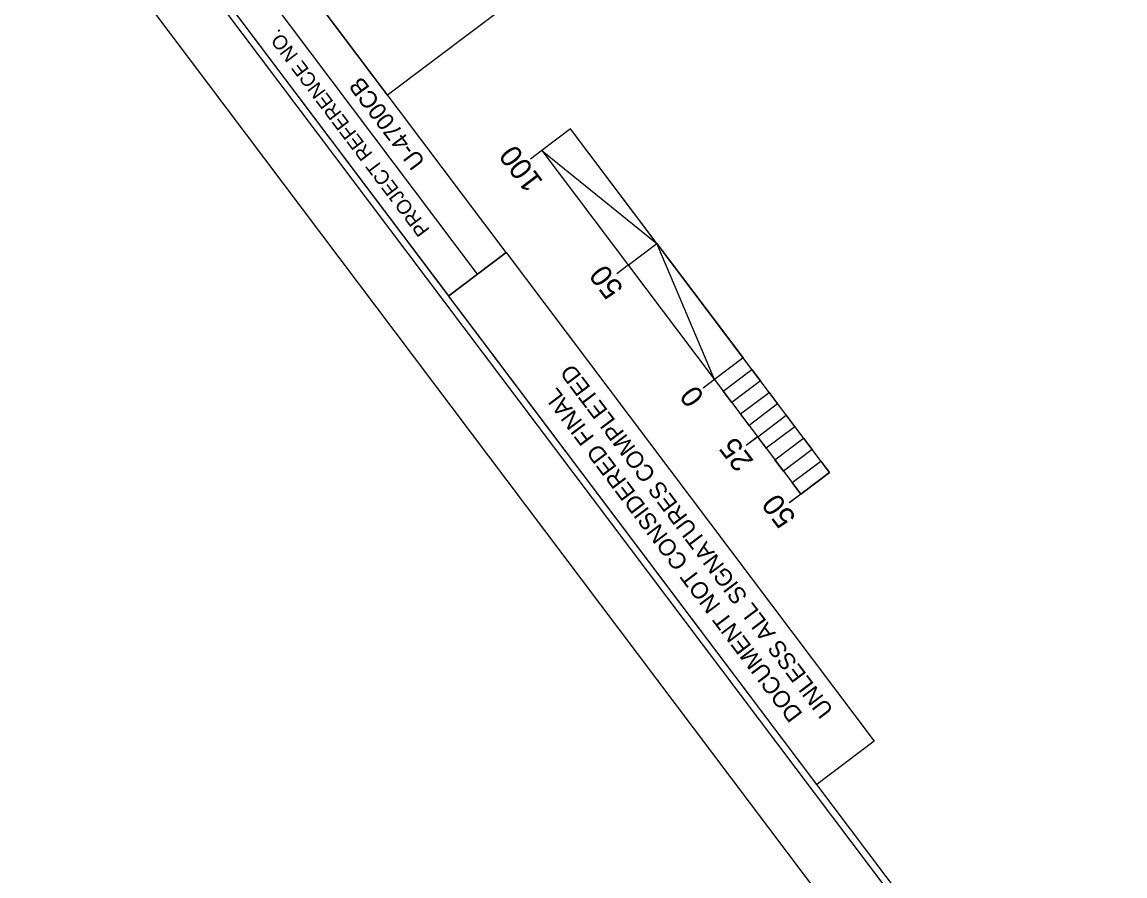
# Model space of a CAD drawing. Extents: x 1262917 to 1264804, y 775326 to 777329.
# Drawn here: x 1262916.5 to 1263300.5, y 776308.6 to 776605.9 of the extents above; entities that cross this region are included whole.
import ezdxf

# ---------------------------------------------------------------- set-up
doc = ezdxf.new("R2010")
doc.units = 0
for name, color, linetype in [('Sheet Data Field CELL', 7, 'Continuous'), ('Sheet Plan CELL', 7, 'Continuous'), ('Sheet Plot Border Inside CELL', 7, 'Continuous'), ('Sheet Plot Border Outside CELL', 7, 'Continuous'), ('Sheet Sticker Exception Certification CELL', 7, 'Continuous'), ('Sheet Title CELL', 7, 'Continuous'), ('Sheet Typical CELL', 7, 'Continuous')]:
    doc.layers.add(name, color=color, linetype=linetype)

msp = doc.modelspace()

# ---------------------------------------------------------------- linework, layer by layer
at = {"layer": 'Sheet Data Field CELL'}
for p, q in [((1263097.51, 776561.19), (1263093.52, 776558.18)), ((1263127.54, 776521.31), (1263123.56, 776518.31)), ((1263172.6, 776461.5), (1263168.61, 776458.5)), ((1263187.61, 776441.56), (1263183.63, 776438.56))]:
    msp.add_line(p, q, dxfattribs=at)
at = {"layer": 'Sheet Plan CELL'}
msp.add_lwpolyline([(1263054.56, 776753.11), (1263133.61, 776648.16), (1263043.77, 776580.5), (1262964.72, 776685.44)], dxfattribs=at)
at = {"layer": 'Sheet Plot Border Inside CELL'}
msp.add_lwpolyline([(1264780.22, 775982.89), (1263777.88, 777313.61), (1262935.19, 776678.9), (1263937.52, 775348.16)], close=True, dxfattribs=at)
at = {"layer": 'Sheet Plot Border Outside CELL'}
msp.add_lwpolyline([(1262916.5, 776670.46), (1263929.36, 775325.74), (1264804.01, 775984.53), (1263791.15, 777329.26)], close=True, dxfattribs=at)
at = {"layer": 'Sheet Sticker Exception Certification CELL'}
for p, q in [((1263065.04, 776510.63), (1263085.04, 776525.69)), ((1263085.03, 776525.68), (1263213.21, 776355.5)), ((1263193.22, 776340.44), (1263065.03, 776510.62)), ((1263213.21, 776355.5), (1263193.22, 776340.44))]:
    msp.add_line(p, q, dxfattribs=at)
at = {"layer": 'Sheet Title CELL'}
for p, q in [((1263107.5, 776568.7), (1263097.52, 776561.18)), ((1263197.59, 776449.06), (1263107.5, 776568.7)), ((1263097.52, 776561.18), (1263093.53, 776558.18)), ((1263097.52, 776561.18), (1263187.63, 776441.56)), ((1263127.56, 776521.31), (1263137.52, 776528.82)), ((1263127.56, 776521.31), (1263123.58, 776518.31)), ((1263157.6, 776481.44), (1263153.61, 776478.44)), ((1263166.6, 776469.47), (1263176.57, 776476.98)), ((1263172.62, 776461.5), (1263168.62, 776458.49)), ((1263187.63, 776441.56), (1263197.59, 776449.06)), ((1263187.63, 776441.56), (1263183.65, 776438.56)), ((1263187.63, 776441.56), (1263187.63, 776441.56)), ((1263183.65, 776438.56), (1263183.65, 776438.56))]:
    msp.add_line(p, q, dxfattribs=at)
for points in [[(1263097.52, 776561.18), (1263137.52, 776528.82), (1263107.45, 776568.76)], [(1263157.6, 776481.44), (1263137.52, 776528.82), (1263167.57, 776488.95)], [(1263163.6, 776473.46), (1263160.59, 776477.44), (1263170.57, 776484.96), (1263173.57, 776480.96)], [(1263169.61, 776465.49), (1263166.6, 776469.47), (1263176.57, 776476.98), (1263179.57, 776472.99)], [(1263175.62, 776457.51), (1263172.62, 776461.5), (1263182.58, 776469), (1263185.58, 776465.01)], [(1263181.62, 776449.53), (1263178.62, 776453.53), (1263188.59, 776461.03), (1263191.59, 776457.06)], [(1263187.63, 776441.56), (1263184.62, 776445.54), (1263194.59, 776453.05), (1263197.59, 776449.06)]]:
    msp.add_lwpolyline(points, close=True, dxfattribs=at)
at = {"layer": 'Sheet Typical CELL'}
for p, q in [((1263085.07, 776525.72), (1262964.72, 776685.5)), ((1263075.06, 776518.17), (1262954.71, 776677.96)), ((1263065.04, 776510.63), (1262944.69, 776670.41)), ((1263847.15, 775472.26), (1262944.69, 776670.41)), ((1263085.07, 776525.72), (1263065.04, 776510.63))]:
    msp.add_line(p, q, dxfattribs=at)

# ---------------------------------------------------------------- texts
at = {"layer": 'Sheet Data Field CELL'}
for s, height, p in [('U-4700CB', 6, (1263057.13, 776557.38)), ('100', 7.488, (1263098.14, 776550.38)), ('50', 7.488, (1263126.19, 776513.16)), ('25', 7.488, (1263171.45, 776453.08)), ('50', 7.488, (1263186.26, 776433.41))]:
    msp.add_text(s, height=height, rotation=126.9874, dxfattribs=at).set_placement(p)
at = {"layer": 'Sheet Plan CELL'}
msp.add_text('PROJECT REFERENCE NO.', height=5.0001, rotation=126.9874, dxfattribs=at).set_placement((1263058.65, 776533.6))
at = {"layer": 'Sheet Sticker Exception Certification CELL'}
for s, p in [('UNLESS ALL SIGNATURES COMPLETED', (1263199.25, 776366.32)), ('DOCUMENT NOT CONSIDERED FINAL', (1263188.51, 776365))]:
    msp.add_text(s, height=5.8579, rotation=126.9874, dxfattribs=at).set_placement(p)
at = {"layer": 'Sheet Title CELL'}
msp.add_text('0', height=7.49, rotation=126.9874, dxfattribs=at).set_placement((1263154.35, 776475.55))

doc.saveas('drawing.dxf')
